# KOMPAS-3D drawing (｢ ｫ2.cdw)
File: created 14.09.2016 18:11:26, last saved 24.12.2016 15:27:20.
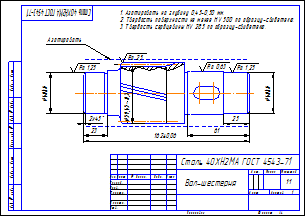
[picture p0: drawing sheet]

Sheet 1: A4, landscape

Title block, sheet 1: name: Вал-шестерня; designation: Сталь 40ХН2МА ГОСТ 4543-71; scale: 1:1; sheets: 1; sheet format: A4; stored path: C:\Users\nikit\OneDrive\Документы\Лабораторные\4 курс\вал.cdw

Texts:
  Никита
  Лит-Масса-Масштаб
  Материал-Предприятие
  Ra 2,5
  Ra 0,63
  Ra 1,25
  1. Азотировать на глубину 0,45-0,50 мм.
  2. Твердость поверхности не менее HV 500 по образцу-свидетелю.
  3. Твердость сердцевины HV 285 по образцу-свидетелю.
  Азотировать
  Масштаб
  Изм.
  Лист
  № докум.
  Подп.
  Дата
  Лит.
  Разраб.
  Пров.
  Т.контр.
  Листов
  Н.контр.
  Утв.
  Инв. № подл.
  Подп. и дата
  Взам. инв. №
  Инв. № дубл.
  Стили документа
Dimensions and other numbers on the sheet: 23; 2 45; 25; 61; 162±0,06; 40; 59,45; 1:1; 1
